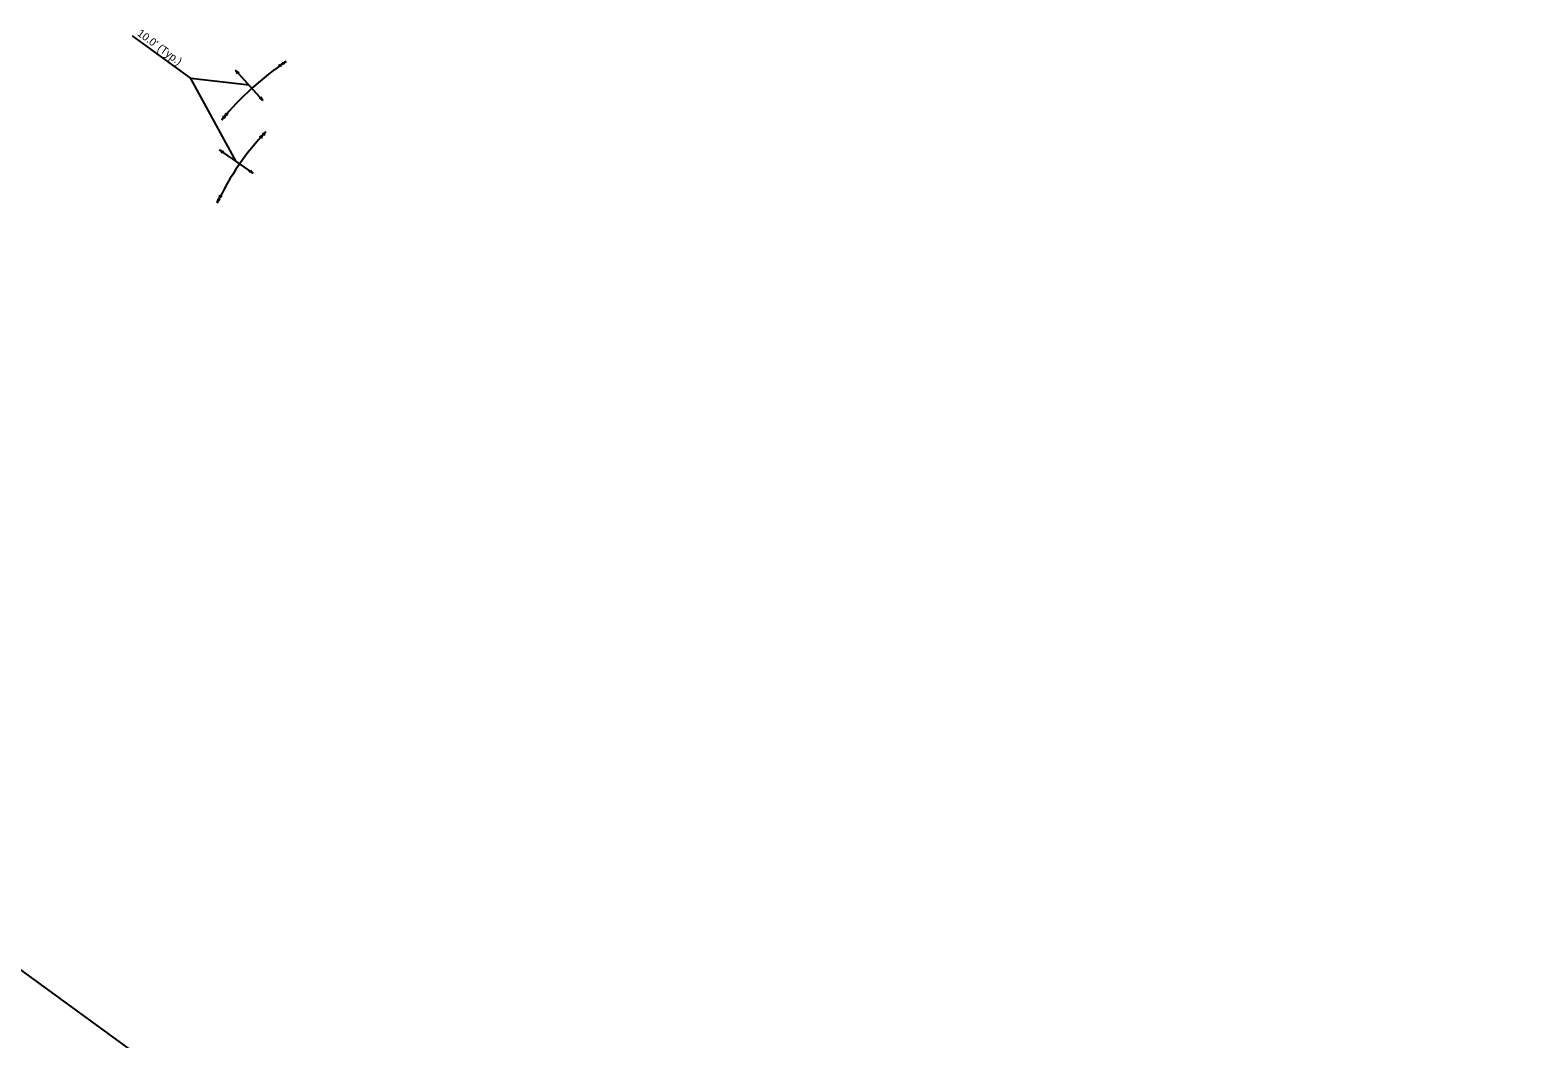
# Model space of a CAD drawing. Extents: x 15567221 to 15568484, y 8782768 to 8783889.
# Drawn here: x 15568115.4 to 15568484, y 8783496.3 to 8783742.9 of the extents above; entities that cross this region are included whole.
import ezdxf

# ---------------------------------------------------------------- set-up
doc = ezdxf.new("R2010")
doc.units = 0
for name, color, linetype in [('Drainage', 7, 'Continuous'), ('EXT_GU', 7, 'Continuous'), ('NamedBoundary', 7, 'Continuous')]:
    doc.layers.add(name, color=color, linetype=linetype)

msp = doc.modelspace()

# ---------------------------------------------------------------- linework, layer by layer
at = {"layer": 'Drainage'}
for p, q in [((15568140.37, 8783741.5), (15568154.72, 8783731.04)), ((15568172.33, 8783725.7), (15568165.6, 8783733.1)), ((15568168.96, 8783729.4), (15568154.72, 8783731.04)), ((15568165.83, 8783710.75), (15568154.72, 8783731.04)), ((15568169.94, 8783707.9), (15568161.72, 8783713.6))]:
    msp.add_line(p, q, dxfattribs=at)
for radius, start, end in [(75, 124.1451, 140.3744), (65, 136.3307, 154.9686)]:
    msp.add_arc((15568220.07, 8783673.15), radius, start, end, dxfattribs=at)
at = {"layer": 'EXT_GU'}
for p, q in [((15568165.6, 8783733.1), (15568165.93, 8783732.74)), ((15568165.6, 8783733.1), (15568166.25, 8783732.39)), ((15568177.18, 8783734.68), (15568176.4, 8783734.13)), ((15568177.18, 8783734.68), (15568176.79, 8783734.4)), ((15568177.98, 8783735.22), (15568177.18, 8783734.68)), ((15568177.98, 8783735.22), (15568177.58, 8783734.95)), ((15568172.33, 8783725.7), (15568171.68, 8783726.41)), ((15568172.33, 8783725.7), (15568172, 8783726.06)), ((15568162.31, 8783720.99), (15568162.92, 8783721.72)), ((15568162.31, 8783720.99), (15568162.62, 8783721.36)), ((15568162.91, 8783721.7), (15568163.53, 8783722.43)), ((15568162.91, 8783721.7), (15568163.22, 8783722.07)), ((15568173.06, 8783718.03), (15568172.4, 8783717.33)), ((15568173.06, 8783718.03), (15568172.72, 8783717.68)), ((15568172.4, 8783717.33), (15568171.75, 8783716.62)), ((15568172.4, 8783717.33), (15568172.07, 8783716.98)), ((15568161.72, 8783713.6), (15568162.12, 8783713.32)), ((15568161.72, 8783713.6), (15568162.51, 8783713.05)), ((15568169.94, 8783707.9), (15568169.15, 8783708.45)), ((15568169.94, 8783707.9), (15568169.54, 8783708.18)), ((15568161.18, 8783700.66), (15568161.59, 8783701.52)), ((15568161.18, 8783700.66), (15568161.39, 8783701.09)), ((15568161.58, 8783701.5), (15568162.01, 8783702.36)), ((15568161.58, 8783701.5), (15568161.79, 8783701.93))]:
    msp.add_line(p, q, dxfattribs=at)
for centre, radius, start, end in [((15568164.03, 8783731.67), 2.12, 14.1873, 42.2597), ((15568167.17, 8783734.53), 2.12, 222.2597, 250.3322), ((15568166.8, 8783731.78), 0.821, 114.5264, 149.9931), ((15568175.96, 8783736.42), 2.12, 277.1462, 305.2187), ((15568175.73, 8783733.65), 0.821, 17.4853, 52.9521), ((15568178.41, 8783732.94), 2.12, 125.2187, 153.2912), ((15568176.77, 8783736.98), 2.12, 276.4311, 304.5036), ((15568176.51, 8783734.21), 0.821, 16.7703, 52.237), ((15568179.18, 8783733.47), 2.12, 124.5036, 152.5761), ((15568171.13, 8783727.02), 0.821, 294.5264, 329.9931), ((15568170.75, 8783724.27), 2.12, 42.2598, 70.3322), ((15568173.9, 8783727.13), 2.12, 194.1873, 222.2598), ((15568160.68, 8783722.35), 2.12, 320.0178, 348.0903), ((15568163.93, 8783719.62), 2.12, 111.9453, 140.0178), ((15568163.45, 8783722.35), 0.821, 212.2844, 247.7511), ((15568161.29, 8783723.09), 2.12, 319.3027, 347.3752), ((15568164.52, 8783720.31), 2.12, 111.2302, 139.3027), ((15568164.07, 8783723.05), 0.821, 211.5693, 247.0361), ((15568171.51, 8783719.49), 2.12, 288.7491, 316.8216), ((15568171.84, 8783716.74), 0.821, 29.0882, 64.5549), ((15568174.61, 8783716.58), 2.12, 136.8216, 164.8941), ((15568170.83, 8783718.77), 2.12, 289.4642, 317.5367), ((15568171.2, 8783716.02), 0.821, 29.8033, 65.27), ((15568173.97, 8783715.9), 2.12, 137.5367, 165.6092), ((15568160.51, 8783711.85), 2.12, 27.2029, 55.2754), ((15568162.93, 8783715.34), 2.12, 235.2754, 263.3479), ((15568163.18, 8783712.58), 0.821, 127.542, 163.0087), ((15568168.47, 8783708.92), 0.821, 307.542, 343.0087), ((15568168.73, 8783706.15), 2.12, 55.2754, 83.3479), ((15568171.15, 8783709.65), 2.12, 207.2029, 235.2754), ((15568159.26, 8783701.57), 2.12, 334.485, 2.5575), ((15568163.1, 8783699.74), 2.12, 126.4125, 154.485), ((15568161.95, 8783702.26), 0.821, 226.7517, 262.2184), ((15568159.67, 8783702.44), 2.12, 333.7699, 1.8424), ((15568163.49, 8783700.56), 2.12, 125.6974, 153.7699), ((15568162.37, 8783703.1), 0.821, 226.0366, 261.5033)]:
    msp.add_arc(centre, radius, start, end, dxfattribs=at)
at = {"layer": 'NamedBoundary'}
msp.add_lwpolyline([(15568248.32, 8782919.55), (15568483.96, 8783242.77), (15567982.56, 8783608.32), (15567746.92, 8783285.1)], close=True, dxfattribs=at)

# ---------------------------------------------------------------- texts
at = {"layer": 'Drainage'}
msp.add_text("10.0' (Typ.)", height=1.8898, rotation=323.7364, dxfattribs=at).set_placement((15568141.46, 8783741.74))

doc.saveas('drawing.dxf')
